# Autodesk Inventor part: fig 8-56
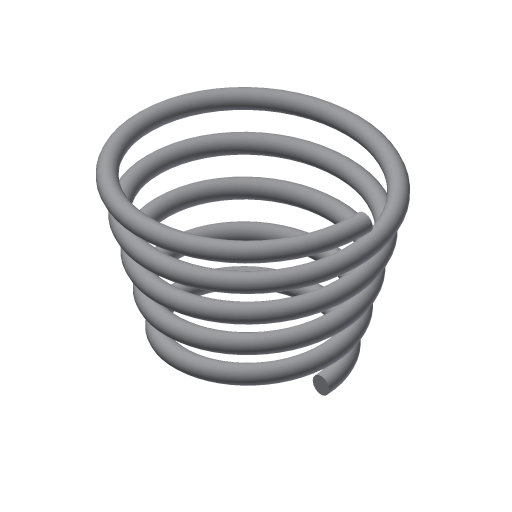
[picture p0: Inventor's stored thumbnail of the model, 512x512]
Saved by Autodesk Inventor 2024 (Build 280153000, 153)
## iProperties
Shininess: 77.0
Length Units: 11269
Angle Units: 11279
Time Units: 11290
Mass Units: 11283
Length Display Precision: 3
Angle Display Precision: 2
Created: 2002-01
Part Number: fig 8-56
Document SubType Name: Modeling
Designer: CADSoft
Density: 1 g/cm^3
Material: Generic
Appearance: Default
Density: 0.0
Volumn: 0.0
Area: 0.0
PropertySet Name: Model Information
Control State: 0
Master: False
Checked Out: False
Author: CADSoft
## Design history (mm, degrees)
sketch "Sketch2"
  geometry: C1 r 2.5 at (-19.895, -0.092)
  constraints: 1 centre point
  dimensions: "d0" = 5 diameter of C1
coil "Coil5" sketch "Sketch2" pitch "d35" = 10; turns "d37" = 5; dims "d36" = 10, "d38" = 15 deg, angle "d39" = 90 deg, angle "d40" = 90 deg, "d41" = 0, "d42" = 0
body "Solid1"
